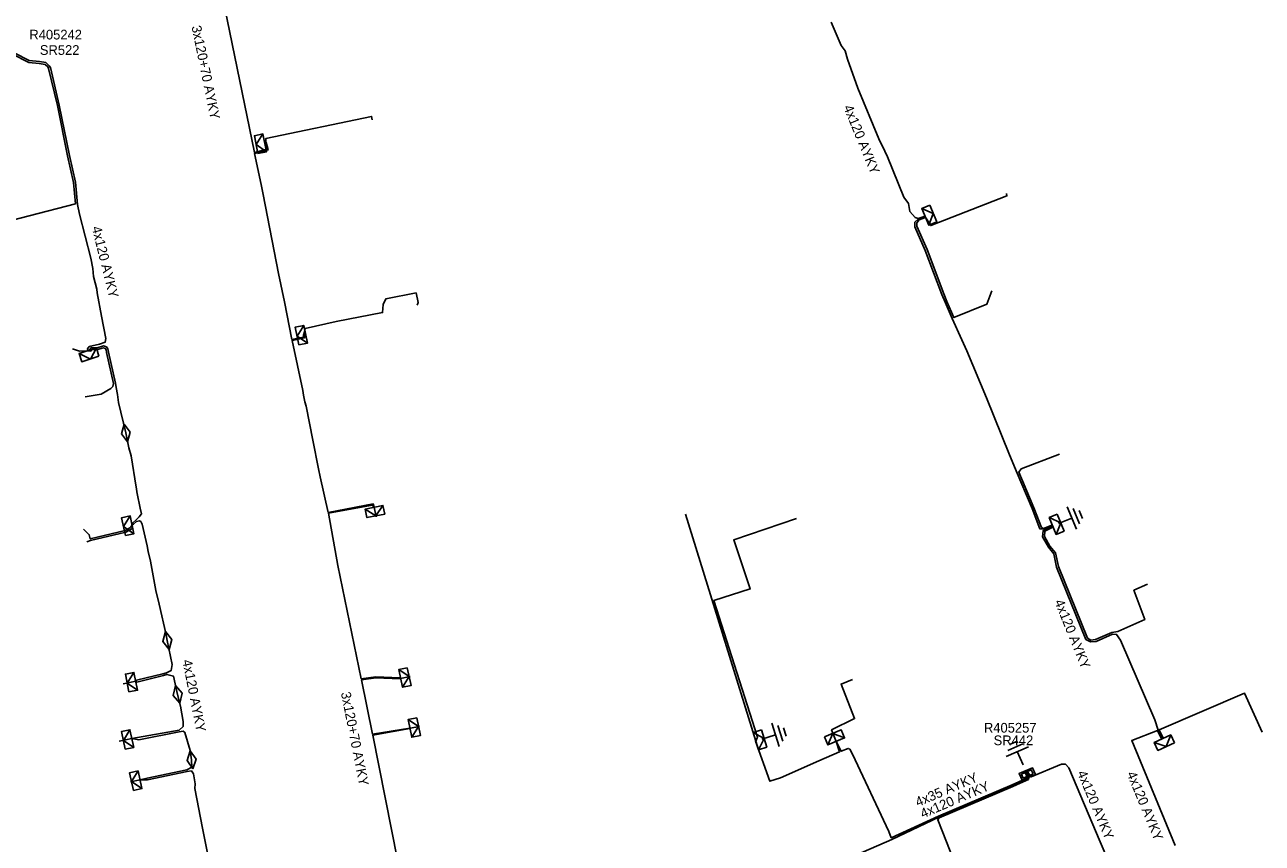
# Model space of a CAD drawing. Extents: x -540028 to -538776, y -1157064 to -1155670.
# Drawn here: x -539732.2 to -539604.5, y -1155898.3 to -1155813.9 of the extents above; entities that cross this region are included whole.
import ezdxf

# ---------------------------------------------------------------- set-up
doc = ezdxf.new("R2010")
doc.units = 0
for name, color, linetype in [('Vrstva 15', 7, 'Continuous'), ('Vrstva 19', 7, 'Continuous'), ('Vrstva 2', 7, 'Continuous'), ('Vrstva 28', 7, 'Continuous'), ('Vrstva 29', 7, 'Continuous'), ('Vrstva 30', 7, 'Continuous'), ('Vrstva 31', 7, 'Continuous'), ('Vrstva 5', 7, 'Continuous'), ('Vrstva 52', 7, 'Continuous'), ('Vrstva 59', 7, 'Continuous'), ('Vrstva 6', 7, 'Continuous')]:
    doc.layers.add(name, color=color, linetype=linetype)

# ---------------------------------------------------------------- blocks, each defined once
blk = doc.blocks.new('17')
at = {"layer": 'Vrstva 2'}
blk.add_lwpolyline([(-1.875, 0), (0, 0.9375), (1.875, 0), (0, -0.9375)], close=True, dxfattribs=at)
blk = doc.blocks.new('132')
at = {"layer": 'Vrstva 2'}
for points in [[(-1.5, 1.5), (1.5, 1.5), (1.5, 0), (-1.5, 0)], [(-1.1, 1.2), (1.1, 1.2), (1.1, 0.3), (-1.1, 0.3)]]:
    blk.add_lwpolyline(points, close=True, dxfattribs=at)
blk = doc.blocks.new('23')
at = {"layer": 'Vrstva 2'}
blk.add_lwpolyline([(1.875, -1.8), (-1.875, -1.8), (-1.875, 0), (1.875, 0)], close=True, dxfattribs=at)
blk.add_lwpolyline([(1.875, 0), (0, -1.8), (-1.875, 0)], dxfattribs=at)
blk = doc.blocks.new('11')
at = {"layer": 'Vrstva 2'}
for p, q in [((0, -4.3), (0, -1.3)), ((-2.5, -4.3), (2.5, -4.3)), ((-1.7, -5.3), (1.7, -5.3)), ((-0.9, -6.3), (0.9, -6.3))]:
    blk.add_line(p, q, dxfattribs=at)

msp = doc.modelspace()

# ---------------------------------------------------------------- linework, layer by layer
at = {"layer": 'Vrstva 5'}
for points in [[(-539714.12, -1155810.3), (-539712.05, -1155809.6), (-539708.5, -1155827.03), (-539707.21, -1155826.69), (-539707.35, -1155826.13), (-539707.43, -1155826.04)], [(-539648.95, -1155813.6), (-539647.94, -1155815.98), (-539647.53, -1155816.54), (-539647.28, -1155817.41), (-539646.21, -1155820.39), (-539644.06, -1155825.62), (-539643.44, -1155826.9), (-539643.16, -1155827.48), (-539641.46, -1155831.64), (-539640.99, -1155832.29), (-539640.86, -1155833.12), (-539640.3, -1155833.74), (-539640, -1155833.85), (-539639.38, -1155833.64), (-539639.27, -1155833.68), (-539639.98, -1155833.91), (-539640.32, -1155834.23), (-539640.34, -1155834.69), (-539639.25, -1155837.14), (-539637.53, -1155841.69), (-539637.21, -1155842.49), (-539636.48, -1155844.15), (-539635.47, -1155846.38), (-539634.96, -1155847.49), (-539632.94, -1155852.37), (-539630.56, -1155858.23), (-539629.76, -1155860.12), (-539629.39, -1155861.01), (-539628.22, -1155863.78), (-539627.43, -1155865.86), (-539627.01, -1155865.92), (-539626.24, -1155865.59), (-539626.11, -1155865.58)], [(-539733.29, -1155816.74), (-539731.73, -1155817.54), (-539730.68, -1155817.64), (-539730.01, -1155817.76), (-539729.67, -1155818.08), (-539729.54, -1155818.28), (-539728.63, -1155822.15), (-539727.57, -1155827.34), (-539726.97, -1155830.1), (-539726.76, -1155832.4), (-539726.54, -1155833.4), (-539725.39, -1155837.95), (-539725.17, -1155839.02), (-539725.09, -1155839.84), (-539724.76, -1155841.14), (-539724.71, -1155841.52), (-539724.27, -1155843.93), (-539723.82, -1155846.23), (-539723.89, -1155846.6), (-539724.47, -1155846.8), (-539725.54, -1155847.07), (-539725.72, -1155847.31), (-539725.7, -1155847.49), (-539725.5, -1155847.39), (-539725.32, -1155847.15), (-539724.71, -1155847.18), (-539724.07, -1155847), (-539723.77, -1155847.1), (-539723.61, -1155847.31), (-539723.56, -1155847.64), (-539722.83, -1155850.84), (-539722.76, -1155851.28), (-539722.64, -1155852.02), (-539722.52, -1155852.82), (-539721.76, -1155855.98), (-539721.45, -1155857.52), (-539721.21, -1155858.33), (-539720.7, -1155861.56), (-539720.66, -1155861.76), (-539720.62, -1155862.07), (-539720.59, -1155862.23), (-539720.27, -1155863.73), (-539720.14, -1155864.33), (-539720.39, -1155864.62), (-539720.69, -1155864.94), (-539721.07, -1155865.3), (-539721.12, -1155865.47), (-539720.96, -1155865.4), (-539720.66, -1155865.11), (-539720.34, -1155865.05), (-539720.21, -1155865.13), (-539720.09, -1155865.4), (-539719.57, -1155867.62), (-539719.46, -1155868.21), (-539719.23, -1155869.22), (-539718.66, -1155872.22), (-539718.32, -1155873.65), (-539717.61, -1155876.82), (-539717.49, -1155877.39), (-539716.98, -1155879.86), (-539717.07, -1155880.49), (-539717.57, -1155880.72), (-539717.94, -1155880.83), (-539720.66, -1155881.5), (-539720.74, -1155881.61), (-539720.62, -1155881.68), (-539717.88, -1155881), (-539717.53, -1155880.89), (-539716.85, -1155881.06), (-539716.42, -1155882.96), (-539716.12, -1155884.16), (-539715.85, -1155885.76), (-539715.86, -1155886.27), (-539716.27, -1155886.66), (-539721.14, -1155887.52), (-539720.42, -1155887.64), (-539716.25, -1155886.81), (-539715.85, -1155886.76), (-539715.67, -1155886.89), (-539715.11, -1155888.76), (-539714.97, -1155889.71), (-539714.95, -1155890.48), (-539715.46, -1155890.75), (-539719.56, -1155891.59), (-539720.3, -1155891.77), (-539719.54, -1155891.79), (-539715.44, -1155890.9), (-539714.99, -1155890.84), (-539714.79, -1155891.16), (-539714.61, -1155892.2), (-539714.65, -1155892.68), (-539713.86, -1155896.75), (-539713.19, -1155900.03)], [(-539707.43, -1155826.04), (-539707.27, -1155826.01), (-539707.09, -1155826.77), (-539708.48, -1155827.13), (-539707.78, -1155830.35), (-539707.58, -1155831.38), (-539706.02, -1155839.53), (-539705.38, -1155842.45), (-539704.62, -1155846.33), (-539703.44, -1155846.09), (-539703.43, -1155845.85), (-539703.21, -1155845.8)], [(-539703.21, -1155845.8), (-539703.34, -1155846.17), (-539704.6, -1155846.43), (-539703.51, -1155851.58), (-539703.42, -1155852.09), (-539703.29, -1155852.76), (-539703.16, -1155853.22), (-539702.45, -1155856.71), (-539701.87, -1155859.69), (-539701.69, -1155860.52), (-539700.87, -1155864.17), (-539696.24, -1155863.3), (-539696.13, -1155863.63), (-539696.14, -1155863.65), (-539696.16, -1155863.64), (-539696.32, -1155863.42), (-539700.85, -1155864.27), (-539699.89, -1155869.65), (-539697.46, -1155881.34), (-539695.95, -1155881.15), (-539693.47, -1155881.25), (-539693.4, -1155881.31), (-539693.45, -1155881.35), (-539695.95, -1155881.25), (-539697.44, -1155881.44), (-539696.29, -1155887.07), (-539692.46, -1155886.45), (-539692.43, -1155886.46), (-539692.45, -1155886.49), (-539696.27, -1155887.17), (-539692.42, -1155906.62)], [(-539626.11, -1155865.58), (-539626.2, -1155865.67), (-539627.1, -1155866.07), (-539627.16, -1155866.7), (-539626.55, -1155867.77), (-539626, -1155868.45), (-539625.7, -1155869.82), (-539622.67, -1155877.28), (-539622.2, -1155877.55), (-539621.61, -1155877.51), (-539619.92, -1155876.74), (-539619.51, -1155876.77), (-539619.09, -1155877.37), (-539615.56, -1155885.59), (-539615.21, -1155886.65), (-539614.77, -1155887.53), (-539614.9, -1155887.49), (-539615.3, -1155886.69), (-539617.94, -1155887.72), (-539613.46, -1155898.55)], [(-539648.44, -1155887.81), (-539648.09, -1155888.9), (-539650.25, -1155889.8), (-539654.2, -1155891.56), (-539655.31, -1155891.92), (-539656.76, -1155887.77)], [(-539629, -1155890.88), (-539628.73, -1155891.47), (-539628.76, -1155891.6), (-539629.22, -1155891.8), (-539630.29, -1155892.28), (-539637.9, -1155895.53), (-539642.77, -1155897.75), (-539643, -1155897.09), (-539646.78, -1155889.12), (-539647.05, -1155888.6), (-539647.22, -1155888.54), (-539647.92, -1155888.83), (-539648.44, -1155887.81)], [(-539620.47, -1155902.98), (-539620.21, -1155902.81), (-539619.6, -1155902.64), (-539619.44, -1155902.46), (-539619.6, -1155902.04), (-539620.25, -1155900.41), (-539621.2, -1155898.17), (-539624.42, -1155890.52), (-539624.79, -1155890.17), (-539625.2, -1155890.15), (-539628.31, -1155891.47), (-539628.46, -1155891.33), (-539628.76, -1155890.77)], [(-539628.92, -1155890.84), (-539628.62, -1155891.47), (-539628.68, -1155891.67), (-539629.18, -1155891.89), (-539630.25, -1155892.37), (-539637.86, -1155895.62), (-539642.69, -1155897.93), (-539650.15, -1155901.16)]]:
    msp.add_lwpolyline(points, dxfattribs=at)
at = {"layer": 'Vrstva 52'}
for points in [[(-539733.54, -1155816.84), (-539731.79, -1155817.74), (-539730.71, -1155817.84), (-539730.1, -1155817.95), (-539729.82, -1155818.21), (-539729.73, -1155818.36), (-539728.83, -1155822.19), (-539727.77, -1155827.38), (-539727.17, -1155830.13), (-539726.97, -1155832.32), (-539736.57, -1155834.8), (-539736.5, -1155835.28)], [(-539707.43, -1155826.04), (-539707.31, -1155826.07), (-539707.31, -1155825.59), (-539696.4, -1155823.32), (-539696.35, -1155823.66)], [(-539639.27, -1155833.68), (-539638.69, -1155834.58), (-539630.82, -1155831.52), (-539630.88, -1155831.25)], [(-539639.27, -1155833.68), (-539639.32, -1155833.77), (-539639.9, -1155833.97), (-539640.12, -1155834.29), (-539640.14, -1155834.65), (-539639.07, -1155837.06), (-539637.35, -1155841.61), (-539637.03, -1155842.41), (-539636.3, -1155844.07), (-539632.89, -1155842.68), (-539632.38, -1155841.3)], [(-539703.21, -1155845.8), (-539703.38, -1155845.79), (-539703.26, -1155845.19), (-539700.07, -1155844.48), (-539695.27, -1155843.56), (-539695.19, -1155842.73), (-539694.94, -1155842.15), (-539691.81, -1155841.52), (-539691.6, -1155842.52), (-539691.68, -1155842.78)], [(-539725.7, -1155847.49), (-539726.54, -1155847.55), (-539727.26, -1155847.31)], [(-539725.7, -1155847.49), (-539725.37, -1155847.55), (-539725.22, -1155847.35), (-539724.69, -1155847.38), (-539724.07, -1155847.21), (-539723.89, -1155847.27), (-539723.8, -1155847.39), (-539723.76, -1155847.68), (-539723.03, -1155850.88), (-539723.12, -1155851.2), (-539723.3, -1155851.38), (-539724.31, -1155851.98), (-539725.97, -1155852.25)], [(-539626.11, -1155865.58), (-539626.25, -1155865.52), (-539627.05, -1155865.83), (-539627.27, -1155865.72), (-539628.04, -1155863.7), (-539629.21, -1155860.93), (-539629.58, -1155860.04), (-539629.34, -1155859.69), (-539625.4, -1155858.16)], [(-539721.12, -1155865.47), (-539721.27, -1155865.73), (-539721.84, -1155866.04), (-539725.45, -1155866.89), (-539725.54, -1155866.48), (-539726.14, -1155865.9)], [(-539721.12, -1155865.47), (-539721.09, -1155865.85), (-539721.76, -1155866.22), (-539725.41, -1155867.08), (-539725.79, -1155867.21)], [(-539656.75, -1155887.77), (-539656.58, -1155887.36), (-539661.08, -1155873.26), (-539657.31, -1155872.07), (-539659.02, -1155867.02), (-539652.56, -1155864.8)], [(-539626.11, -1155865.58), (-539626.16, -1155865.72), (-539626.9, -1155866.1), (-539626.96, -1155866.66), (-539626.39, -1155867.65), (-539625.82, -1155868.35), (-539625.5, -1155869.76), (-539622.51, -1155877.14), (-539622.16, -1155877.35), (-539621.67, -1155877.31), (-539620, -1155876.56), (-539619.39, -1155876.47), (-539616.6, -1155875.24), (-539617.72, -1155872.21), (-539616.32, -1155871.58)], [(-539648.44, -1155887.81), (-539648.93, -1155886.62), (-539646.55, -1155885.46), (-539647.95, -1155881.89), (-539646.78, -1155881.42)], [(-539614.77, -1155887.53), (-539614.75, -1155887.41), (-539615.12, -1155886.61), (-539606.3, -1155882.84), (-539604.47, -1155886.85)], [(-539628.84, -1155890.81), (-539628.52, -1155891.46), (-539628.6, -1155891.74), (-539629.14, -1155891.98), (-539630.21, -1155892.46), (-539637.82, -1155895.71), (-539637.97, -1155895.92), (-539636.22, -1155900.28)]]:
    msp.add_lwpolyline(points, dxfattribs=at)
at = {"layer": 'Vrstva 59'}
for points in [[(-539696.14, -1155863.65), (-539695.94, -1155864.63)], [(-539656.75, -1155887.77), (-539663.99, -1155864.36)], [(-539693.4, -1155881.31), (-539692.42, -1155881.1)], [(-539720.74, -1155881.61), (-539722.05, -1155881.87)], [(-539692.43, -1155886.46), (-539691.45, -1155886.26)], [(-539721.14, -1155887.52), (-539722.46, -1155887.8)], [(-539720.3, -1155891.77), (-539721.28, -1155891.98)]]:
    msp.add_lwpolyline(points, dxfattribs=at)

# ---------------------------------------------------------------- block references
at = {"layer": 'Vrstva 15', "xscale": 0.5}
for p, yscale, rotation in [((-539626.11, -1155865.58), 0.5, 112.22181113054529), ((-539656.75, -1155887.77), 0.49999999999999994, 107.42304997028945), ((-539628.88, -1155890.83), 0.5, -156.02647508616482)]:
    msp.add_blockref('11', p, dxfattribs=dict(at, yscale=yscale, rotation=rotation))
at = {"layer": 'Vrstva 19'}
for p, xscale, yscale, rotation in [((-539721.76, -1155855.98), 0.5000000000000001, 0.5, -78.6185373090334), ((-539717.49, -1155877.39), 0.5, 0.5000000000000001, -78.33364421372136), ((-539716.42, -1155882.96), 0.49999999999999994, 0.5000000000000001, -75.96375649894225), ((-539714.97, -1155889.71), 0.5, 0.5000000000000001, 98.3832484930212)]:
    msp.add_blockref('17', p, dxfattribs=dict(at, xscale=xscale, yscale=yscale, rotation=rotation))
at = {"layer": 'Vrstva 28', "xscale": 0.5, "yscale": 0.5, "rotation": -156.02647508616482}
msp.add_blockref('132', (-539628.88, -1155890.83), dxfattribs=at)
at = {"layer": 'Vrstva 31'}
for p, xscale, yscale, rotation in [((-539707.43, -1155826.04), 0.5, 0.5, -78.59201390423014), ((-539639.26, -1155833.68), 0.49999999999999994, 0.5, 112.45055825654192), ((-539703.21, -1155845.8), 0.49999999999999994, 0.5000000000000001, -78.59128057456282), ((-539725.7, -1155847.49), 0.5, 0.5000000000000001, 17.66833609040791), ((-539721.12, -1155865.46), 0.5, 0.5, -78.11671941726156), ((-539696.14, -1155863.65), 0.5, 0.5, 11.512758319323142), ((-539626.11, -1155865.58), 0.5, 0.5, 112.22181113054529), ((-539720.74, -1155881.61), 0.5, 0.5, -78.66798883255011), ((-539693.4, -1155881.31), 0.49999999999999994, 0.5, 101.89434171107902), ((-539692.43, -1155886.46), 0.49999999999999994, 0.5000000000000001, 101.26180828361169), ((-539721.14, -1155887.52), 0.5000000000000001, 0.5, -77.98632503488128), ((-539656.75, -1155887.77), 0.49999999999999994, 0.5, 107.42305003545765), ((-539648.44, -1155887.81), 0.5, 0.5, -157.29647500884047), ((-539614.77, -1155887.53), 0.5, 0.5, 24.5154444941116), ((-539720.3, -1155891.77), 0.5000000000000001, 0.5, -77.67750278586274)]:
    msp.add_blockref('23', p, dxfattribs=dict(at, xscale=xscale, yscale=yscale, rotation=rotation))

# ---------------------------------------------------------------- texts
at = {"layer": 'Vrstva 29'}
for s, p in [('R405242', (-539731.72, -1155815.37)), ('R405257', (-539633.2, -1155886.9))]:
    msp.add_text(s, height=1, dxfattribs=at).set_placement(p)
at = {"layer": 'Vrstva 30'}
for s, p in [('SR522', (-539730.64, -1155816.96)), ('SR442', (-539632.2, -1155888.2))]:
    msp.add_text(s, height=1, dxfattribs=at).set_placement(p)
at = {"layer": 'Vrstva 6'}
for s, rotation, p in [('3x120+70 AYKY', 281.6, (-539714.99, -1155814.04)), ('4x120 AYKY', 292.347, (-539647.72, -1155822.36)), ('4x120 AYKY', 283.955, (-539725.29, -1155834.77)), ('4x120 AYKY', 292.082, (-539625.94, -1155873.39)), ('4x120 AYKY', 281.251, (-539715.94, -1155879.46)), ('3x120+70 AYKY', 281.199, (-539699.57, -1155882.79)), ('4x35 AYKY', 23.129, (-539640.02, -1155894.58)), ('4x120 AYKY', 292.827, (-539623.6, -1155891.05)), ('4x120 AYKY', 292.473, (-539618.48, -1155891.14)), ('4x120 AYKY', 23.126, (-539639.51, -1155895.77))]:
    msp.add_text(s, height=1, rotation=rotation, dxfattribs=at).set_placement(p)

doc.saveas('drawing.dxf')
